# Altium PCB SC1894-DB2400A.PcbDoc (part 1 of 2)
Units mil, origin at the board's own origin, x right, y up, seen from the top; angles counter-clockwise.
Board outline 1800 x 1000 mil, 4 copper layers (L1 TOP, L2 GND, L3 PWR, L4  BOT), stack 35.4 mil thick; 139 components, 91 nets, 318 pads, 589 vias.
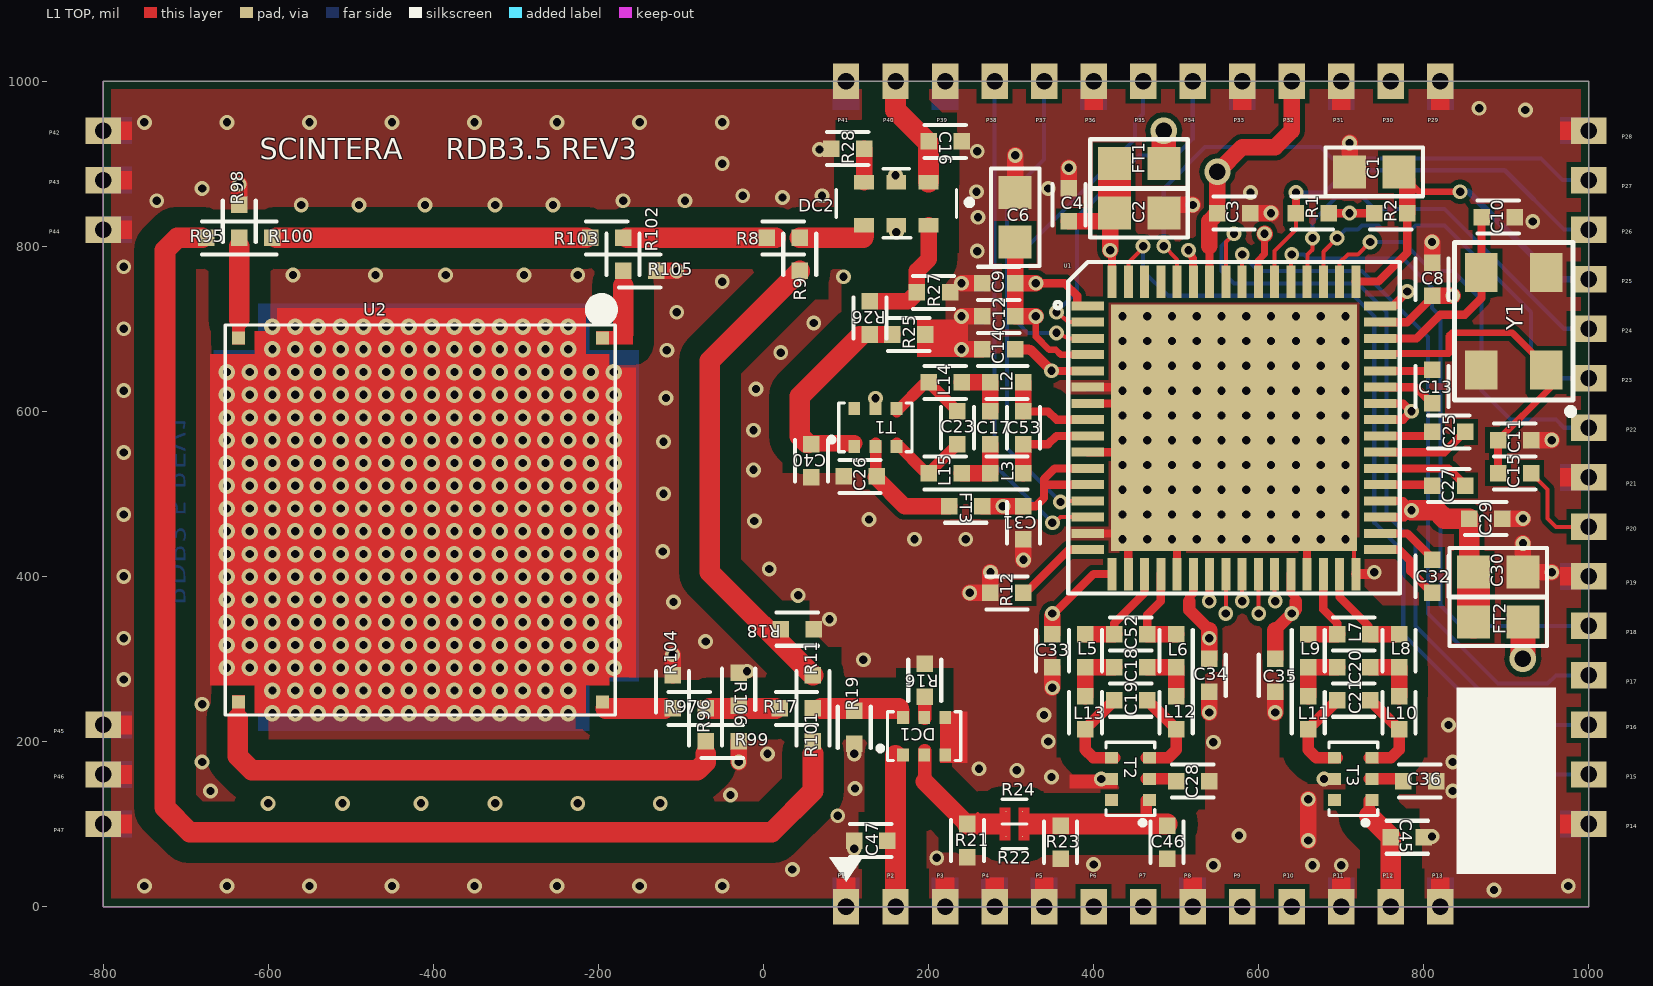
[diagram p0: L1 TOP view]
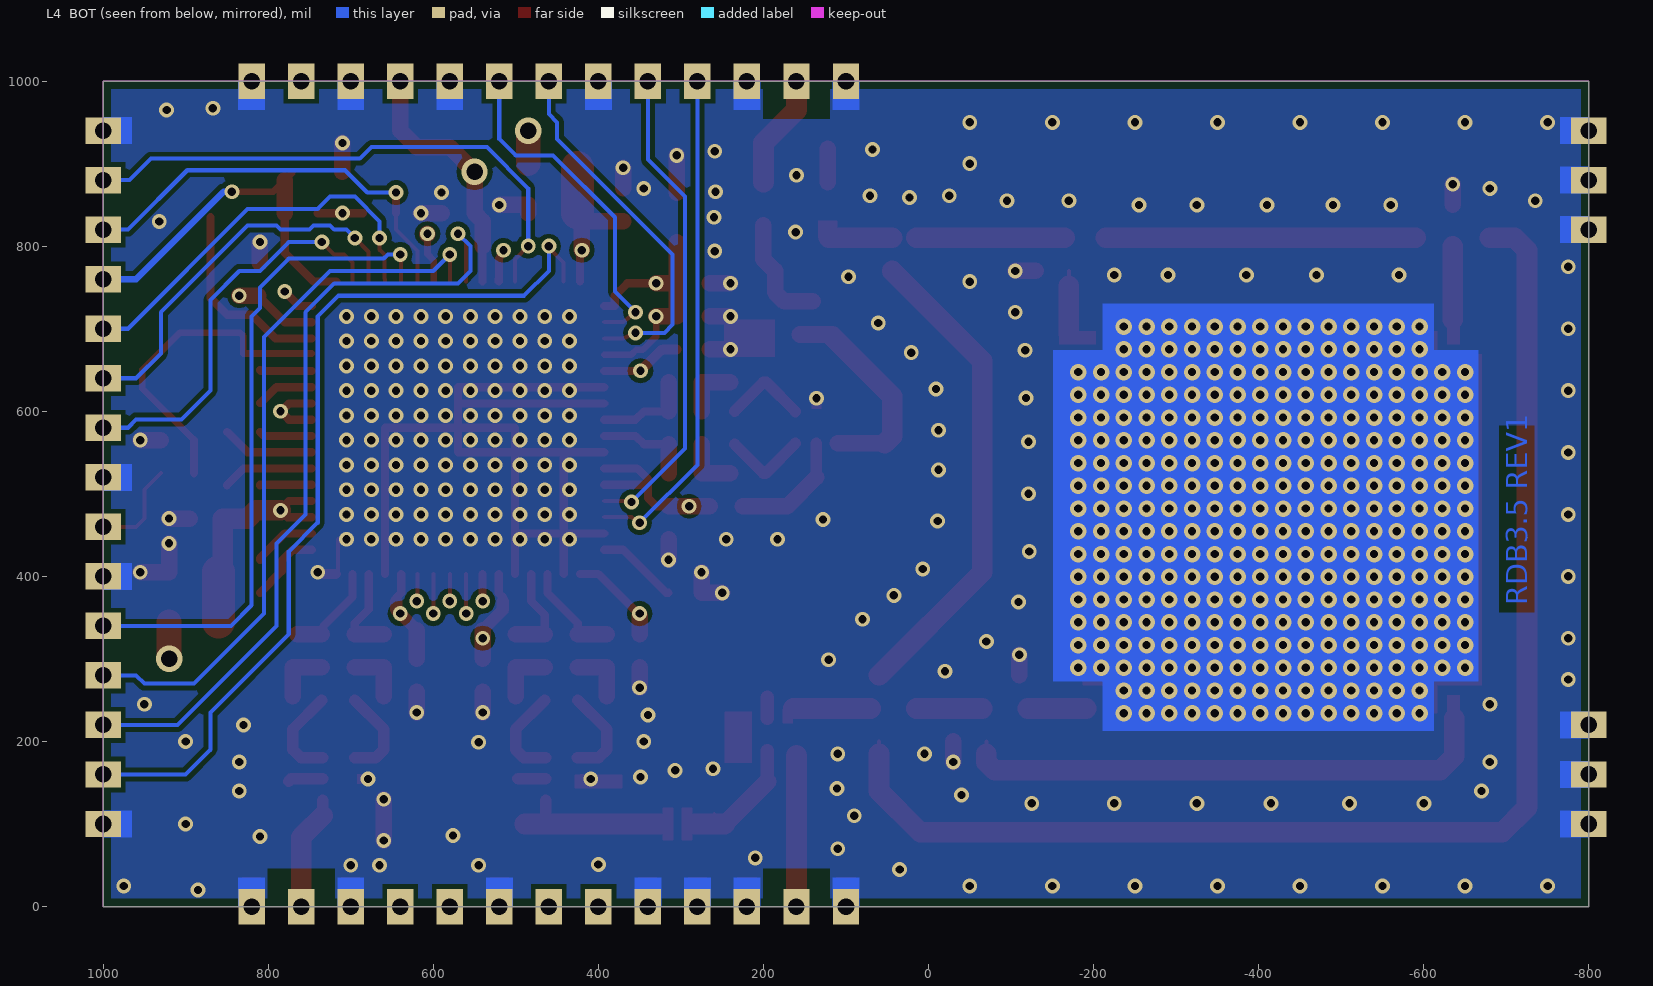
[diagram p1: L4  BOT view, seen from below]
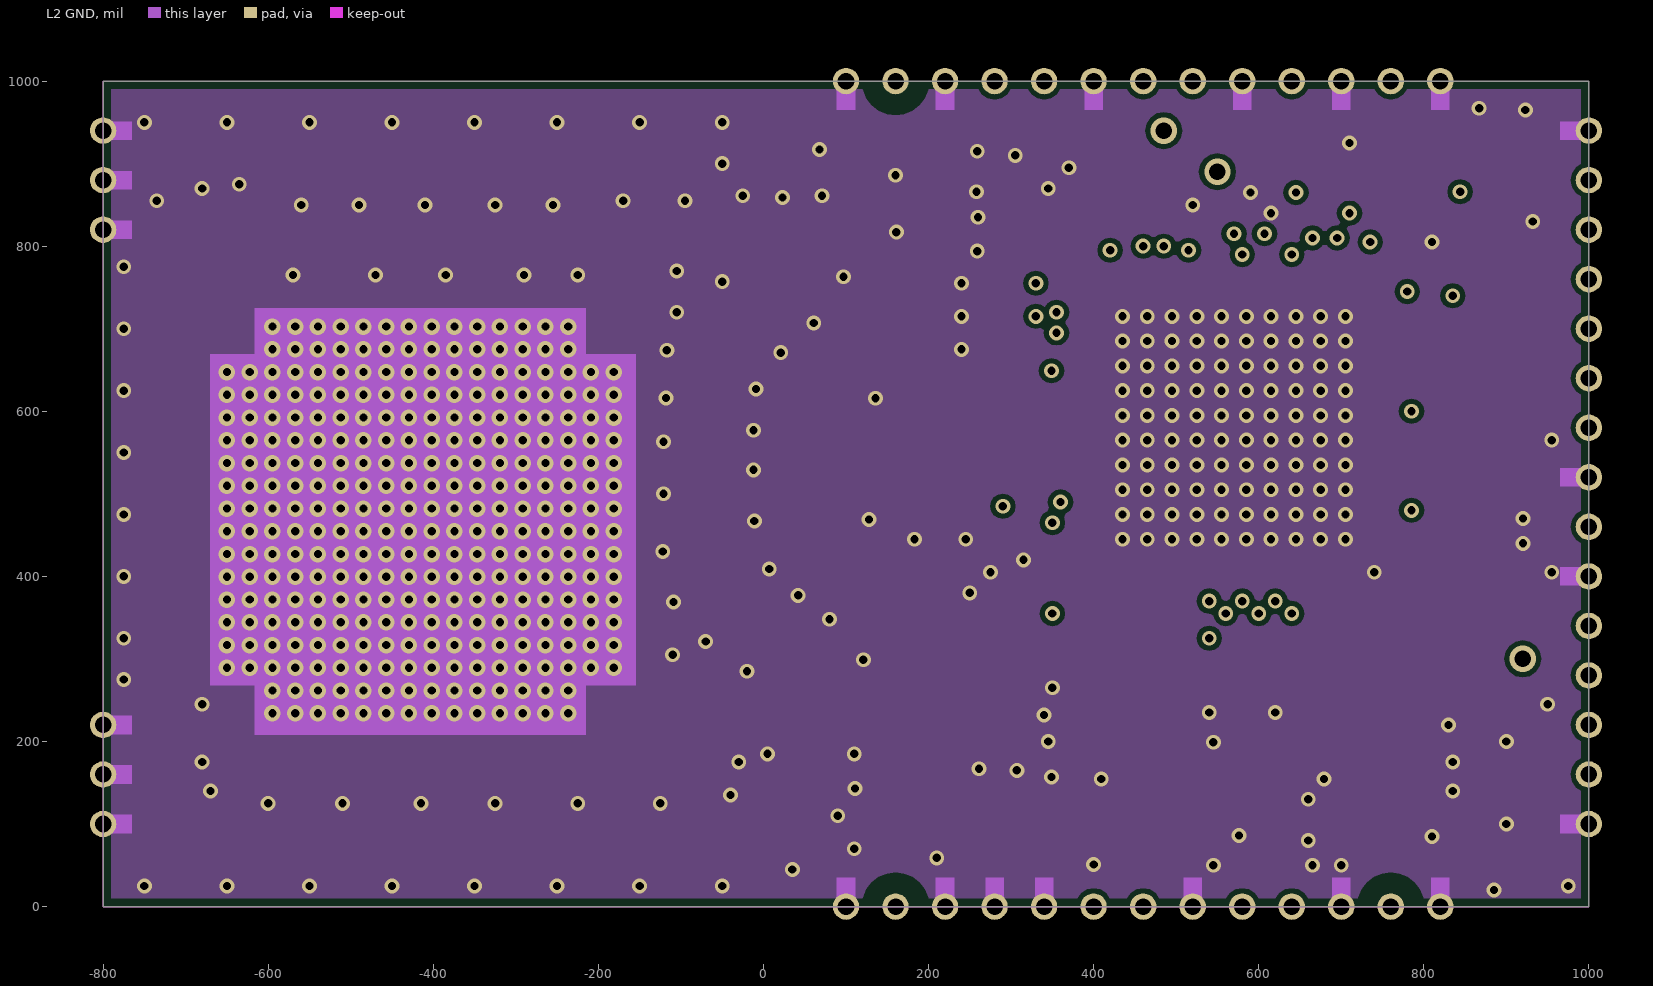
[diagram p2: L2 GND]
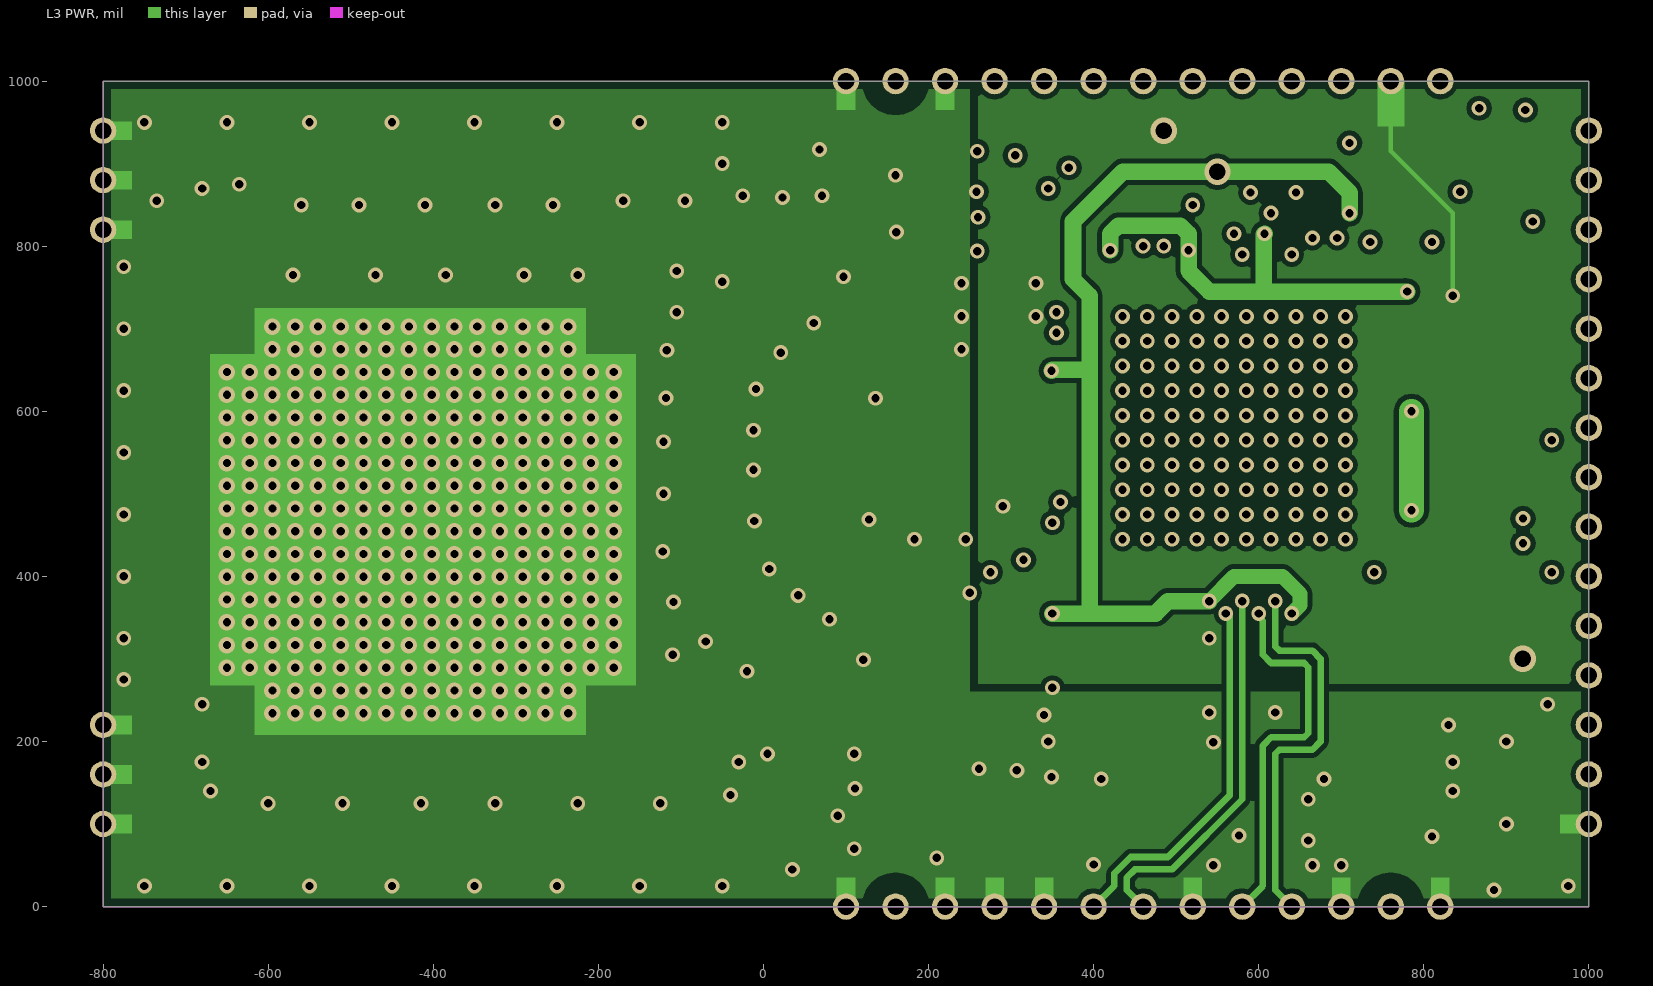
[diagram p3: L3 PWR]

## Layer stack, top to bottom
Solder Mask Top: solder mask 0.4, Solder Resist, Dk 3.5
L1 TOP: signal copper 1.35
Dielectric1: dielectric 10, FR-4, Dk 4.3
L2 GND: signal copper 1.35
Dielectric2: dielectric 10, FR-4, Dk 4.3
L3 PWR: signal copper 1.35
Dielectric3: dielectric 10, FR-4, Dk 4.3
L4  BOT: signal copper 1.35
Solder Mask Bottom: solder mask 0.4, Solder Resist, Dk 3.5

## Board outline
-800,1000 -800,0 1000,0 1000,1000

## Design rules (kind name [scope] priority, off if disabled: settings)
Clearance "RF Trace Clearance" [InNetClass('RF')] p1: gap=25
Clearance "'Default' PADS rule_24" [(IsTrack Or IsArc) vs IsSMTPin] p2: gap=6
Clearance "'Default' PADS rule_23" [IsSMTPin vs (IsTrack Or IsArc)] p3: gap=6
Clearance "'Default' PADS rule_22" [(IsTrack Or IsArc) vs IsThruPin] p4: gap=6
Clearance "'Default' PADS rule_21" [IsThruPin vs (IsTrack Or IsArc)] p5: gap=6
Clearance "'Default' PADS rule_20" [All] p6: gap=6
Clearance "'Default' PADS rule_19" [(IsTrack Or IsArc) vs (IsTrack Or IsArc)] p7: gap=6
Clearance "'Default' PADS rule_18" [All] p8: gap=6
Clearance "'Default' PADS rule_15" [IsVia vs IsVia] p9: gap=6
ComponentClearance "'Default' PADS rule_12" [All] p1: gap=6 collisioncheckmode=3 verticalgap=10 showdistances=FALSE
FlightTimeFalling "'Default' PADS rule_6" [All] p1: maximum=10.00
FlightTimeRising "'Default' PADS rule_5" [All] p1: maximum=10.00
Length "'Default' PADS rule" [All] p1: maxlimit=50000 minlimit=0
MatchedLengths "'Default' PADS rule_7" [InNetClass('All Nets')] p1: tolerance=200 checknetsindiffpair=TRUE checkdiffpairvsdiffpair=TRUE checkothers=TRUE
MaxMinImpedance "'Default' PADS rule_4" [All] p1: minimum=50.00 maximum=150.0
ParallelSegment "'Default' PADS rule_3" [All] p1: limit=1000 gap=200
ParallelSegment "'Default' PADS rule_2" [All] p2: limit=1000 gap=200
PlaneClearance "'Net' PADS rule_50" [InNet('N16778151')] p1: clearance=20
PlaneClearance "'Net' PADS rule_49" [InNet('N16798748')] p2: clearance=20
PlaneClearance "'Net' PADS rule_48" [InNet('GND')] p3: clearance=8
PlaneClearance "'Net' PADS rule_46" [InNet('N16820786')] p4: clearance=20
PlaneClearance "'Net' PADS rule_45" [InNet('N16798802')] p5: clearance=20
PlaneClearance "'Net' PADS rule_44" [InNet('N16778850')] p6: clearance=20
PlaneClearance "'Net' PADS rule_43" [InNet('RFIN')] p7: clearance=20
PlaneClearance "'Net' PADS rule_42" [InNet('N16837562')] p8: clearance=20
PlaneClearance "'Net' PADS rule_41" [InNet('N16905883')] p9: clearance=20
PlaneClearance "'Net' PADS rule_40" [InNet('N16809609')] p10: clearance=20
PlaneClearance "'Net' PADS rule_39" [InNet('N16837983')] p11: clearance=20
PlaneClearance "'Net' PADS rule_38" [InNet('N16886954')] p12: clearance=20
PlaneClearance "'Net' PADS rule_37" [InNet('N16852193')] p13: clearance=20
PlaneClearance "'Net' PADS rule_36" [InNet('N16907208')] p14: clearance=10
PlaneClearance "'Net' PADS rule_35" [InNet('N16864474')] p15: clearance=20
PlaneClearance "'Net' PADS rule_34" [InNet('N16853064')] p16: clearance=20
PlaneClearance "'Net' PADS rule_33" [InNet('N16810438')] p17: clearance=20
PlaneClearance "'Net' PADS rule_32" [InNet('N16780104')] p18: clearance=20
PlaneClearance "'Net' PADS rule_31" [InNet('N16780111')] p19: clearance=20
PlaneClearance "'Net' PADS rule_30" [InNet('N16778643')] p20: clearance=20
PlaneClearance "'Net' PADS rule_29" [InNet('N16778883')] p21: clearance=20
PlaneClearance "'Net' PADS rule_28" [InNet('N16779391')] p22: clearance=20
PlaneClearance "'Net' PADS rule_27" [InNet('N16778942')] p23: clearance=20
PlaneClearance "'Net' PADS rule_26" [InNet('RFFB')] p24: clearance=20
PlaneClearance "'Net' PADS rule_25" [InNet('N16779395')] p25: clearance=20
PlaneClearance "'Net' PADS rule" [InNet('N16780222')] p26: clearance=20
PlaneClearance "'Default' PADS rule_14" [All] p27: clearance=6
PlaneConnect "Power Plane Connect Style - Via from round thru-hole global defaults" [IsVia] p1: planeconnectstyle=Direct reliefexpansion=20 reliefentries=4 reliefconductorwidth=15 reliefairgap=10
PlaneConnect "Power Plane Connect Style - Round thru-hole pad from global defaults" [IsPad And OnMultiLayer And (PadShape_MidLayer1 = 'Round') And (PadXSize_MidLayer1 = PadYSize_MidLayer1)] p2: planeconnectstyle=Direct reliefexpansion=20 reliefentries=4 reliefconductorwidth=15 reliefairgap=10
PlaneConnect "Power Plane Connect Style - Square thru-hole pad from global defaults" [IsPad And OnMultiLayer And ((PadShape_MidLayer1 = 'Rectangular') Or (PadShape_MidLayer1 = 'Octagonal') Or (PadShape_MidLayer1 = 'Rounded Rectangle')) And (PadXSize_MidLayer1 = PadYSize_MidLayer1)] p3: planeconnectstyle=Direct reliefexpansion=20 reliefentries=4 reliefconductorwidth=15 reliefairgap=10
PlaneConnect "Power Plane Connect Style - Rect thru-hole pad from global defaults" [IsPad And OnMultiLayer And ((PadShape_MidLayer1 = 'Rectangular') Or (PadShape_MidLayer1 = 'Octagonal') Or (PadShape_MidLayer1 = 'Rounded Rectangle')) And (PadXSize_MidLayer1 <> PadYSize_MidLayer1)] p4: planeconnectstyle=Direct reliefexpansion=20 reliefentries=4 reliefconductorwidth=15 reliefairgap=10
PlaneConnect "Power Plane Connect Style - Square-rect thru-hole pad from global defaults" [IsPad And OnMultiLayer And (PadShape_MidLayer1 = 'Rounded Rectangle') And (PadXSize_MidLayer1 = PadYSize_MidLayer1) And (Pad_CornerRadius_MidLayer1 = '0%')] p5: planeconnectstyle=Direct reliefexpansion=20 reliefentries=4 reliefconductorwidth=15 reliefairgap=10
PlaneConnect "Power Plane Connect Style - Oval thru-hole pad from global defaults" [IsPad And OnMultiLayer And (PadShape_MidLayer1 = 'Round') And (PadXSize_MidLayer1 <> PadYSize_MidLayer1)] p6: planeconnectstyle=Direct reliefexpansion=20 reliefentries=4 reliefconductorwidth=15 reliefairgap=10
PlaneConnect "Power Plane Connect Style - Round-oval thru-hole pad from global defaults" [IsPad And OnMultiLayer And (PadShape_MidLayer1 = 'Rounded Rectangle') And (PadXSize_MidLayer1 = PadYSize_MidLayer1) And (Pad_CornerRadius_MidLayer1 = '100%')] p7: planeconnectstyle=Direct reliefexpansion=20 reliefentries=4 reliefconductorwidth=15 reliefairgap=10
PolygonConnect "Polygon Connect Style - L4  BOT Round SMD from global defaults" [IsSMTPin And (PadShape_BottomLayer = 'Round') And (PadXSize_BottomLayer = PADYSize_BottomLayer) vs Layer = 'L4  BOT'] p1: connectstyle=Direct reliefconductorwidth=10 reliefentries=4 polygonreliefangle="45 Angle" airgapwidth=10
PolygonConnect "Polygon Connect Style - L1 TOP Round SMD from global defaults" [IsSMTPin And (PadShape_TopLayer = 'Round') And (PadXSize_TopLayer = PADYSize_TopLayer) vs Layer = 'L1 TOP'] p2: connectstyle=Direct reliefconductorwidth=10 reliefentries=4 polygonreliefangle="45 Angle" airgapwidth=10
PolygonConnect "Polygon Connect Style - L4  BOT Square SMD from global defaults 1" [IsSMTPin And (PadShape_BottomLayer = 'Rectangular') And (PadXSize_BottomLayer = PADYSize_BottomLayer) vs Layer = 'L4  BOT'] p3: connectstyle=Direct reliefconductorwidth=10 reliefentries=4 polygonreliefangle="45 Angle" airgapwidth=10
PolygonConnect "Polygon Connect Style - L4  BOT Square SMD from global defaults 2" [IsSMTPin And (PadShape_BottomLayer = 'Octagonal') And (PadXSize_BottomLayer = PADYSize_BottomLayer) vs Layer = 'L4  BOT'] p4: connectstyle=Direct reliefconductorwidth=10 reliefentries=4 polygonreliefangle="45 Angle" airgapwidth=10
PolygonConnect "Polygon Connect Style - L4  BOT Square SMD from global defaults 3" [IsSMTPin And (PadShape_BottomLayer = 'Rounded Rectangle') And (PadXSize_BottomLayer = PADYSize_BottomLayer) vs Layer = 'L4  BOT'] p5: connectstyle=Direct reliefconductorwidth=10 reliefentries=4 polygonreliefangle="45 Angle" airgapwidth=10
PolygonConnect "Polygon Connect Style - L1 TOP Square SMD from global defaults 1" [IsSMTPin And (PadShape_TopLayer = 'Rectangular') And (PadXSize_TopLayer = PADYSize_TopLayer) vs Layer = 'L1 TOP'] p6: connectstyle=Direct reliefconductorwidth=10 reliefentries=4 polygonreliefangle="45 Angle" airgapwidth=10
PolygonConnect "Polygon Connect Style - L1 TOP Square SMD from global defaults 2" [IsSMTPin And (PadShape_TopLayer = 'Octagonal') And (PadXSize_TopLayer = PADYSize_TopLayer) vs Layer = 'L1 TOP'] p7: connectstyle=Direct reliefconductorwidth=10 reliefentries=4 polygonreliefangle="45 Angle" airgapwidth=10
PolygonConnect "Polygon Connect Style - L1 TOP Square SMD from global defaults 3" [IsSMTPin And (PadShape_TopLayer = 'Rounded Rectangle') And (PadXSize_TopLayer = PADYSize_TopLayer) vs Layer = 'L1 TOP'] p8: connectstyle=Direct reliefconductorwidth=10 reliefentries=4 polygonreliefangle="45 Angle" airgapwidth=10
PolygonConnect "Polygon Connect Style - L4  BOT Rect SMD from global defaults 1" [IsSMTPin And (PadShape_BottomLayer = 'Rectangular') And (PadXSize_BottomLayer <> PADYSize_BottomLayer) vs Layer = 'L4  BOT'] p9: connectstyle=Direct reliefconductorwidth=10 reliefentries=4 polygonreliefangle="45 Angle" airgapwidth=10
PolygonConnect "Polygon Connect Style - L4  BOT Rect SMD from global defaults 2" [IsSMTPin And (PadShape_BottomLayer = 'Octagonal') And (PadXSize_BottomLayer <> PADYSize_BottomLayer) vs Layer = 'L4  BOT'] p10: connectstyle=Direct reliefconductorwidth=10 reliefentries=4 polygonreliefangle="45 Angle" airgapwidth=10
PolygonConnect "Polygon Connect Style - L4  BOT Rect SMD from global defaults 3" [IsSMTPin And (PadShape_BottomLayer = 'Rounded Rectangle') And (PadXSize_BottomLayer <> PADYSize_BottomLayer) vs Layer = 'L4  BOT'] p11: connectstyle=Direct reliefconductorwidth=10 reliefentries=4 polygonreliefangle="45 Angle" airgapwidth=10
PolygonConnect "Polygon Connect Style - L4  BOT Square-rect SMD pad from global defaults" [IsSMTPin And (PadShape_BottomLayer = 'Rounded Rectangle') And (PadXSize_BottomLayer = PADYSize_BottomLayer) And (Pad_CornerRadius_BottomLayer = '0%') vs Layer = 'L4  BOT'] p12: connectstyle=Direct reliefconductorwidth=10 reliefentries=4 polygonreliefangle="45 Angle" airgapwidth=10
PolygonConnect "Polygon Connect Style - L1 TOP Rect SMD from global defaults 1" [IsSMTPin And (PadShape_TopLayer = 'Rectangular') And (PadXSize_TopLayer <> PADYSize_TopLayer) vs Layer = 'L1 TOP'] p13: connectstyle=Direct reliefconductorwidth=10 reliefentries=4 polygonreliefangle="45 Angle" airgapwidth=10
PolygonConnect "Polygon Connect Style - L1 TOP Rect SMD from global defaults 2" [IsSMTPin And (PadShape_TopLayer = 'Octagonal') And (PadXSize_TopLayer <> PADYSize_TopLayer) vs Layer = 'L1 TOP'] p14: connectstyle=Direct reliefconductorwidth=10 reliefentries=4 polygonreliefangle="45 Angle" airgapwidth=10
PolygonConnect "Polygon Connect Style - L1 TOP Rect SMD from global defaults 3" [IsSMTPin And (PadShape_TopLayer = 'Rounded Rectangle') And (PadXSize_TopLayer <> PADYSize_TopLayer) vs Layer = 'L1 TOP'] p15: connectstyle=Direct reliefconductorwidth=10 reliefentries=4 polygonreliefangle="45 Angle" airgapwidth=10
PolygonConnect "Polygon Connect Style - L1 TOP Square-rect SMD pad from global defaults" [IsSMTPin And (PadShape_TopLayer = 'Rounded Rectangle') And (PadXSize_TopLayer = PADYSize_TopLayer) And (Pad_CornerRadius_TopLayer = '0%') vs Layer = 'L1 TOP'] p16: connectstyle=Direct reliefconductorwidth=10 reliefentries=4 polygonreliefangle="45 Angle" airgapwidth=10
PolygonConnect "Polygon Connect Style - L4  BOT Oval SMD from global defaults" [IsSMTPin And (PadShape_BottomLayer = 'Round') And (PadXSize_BottomLayer <> PADYSize_BottomLayer) vs Layer = 'L4  BOT'] p17: connectstyle=Direct reliefconductorwidth=10 reliefentries=4 polygonreliefangle="45 Angle" airgapwidth=10
PolygonConnect "Polygon Connect Style - L4  BOT Round-oval SMD pad from global defaults" [IsSMTPin And (PadShape_BottomLayer = 'Rounded Rectangle') And (PadXSize_BottomLayer = PADYSize_BottomLayer) And (Pad_CornerRadius_BottomLayer = '100%') vs Layer = 'L4  BOT'] p18: connectstyle=Direct reliefconductorwidth=10 reliefentries=4 polygonreliefangle="45 Angle" airgapwidth=10
PolygonConnect "Polygon Connect Style - L1 TOP Oval SMD from global defaults" [IsSMTPin And (PadShape_TopLayer = 'Round') And (PadXSize_TopLayer <> PADYSize_TopLayer) vs Layer = 'L1 TOP'] p19: connectstyle=Direct reliefconductorwidth=10 reliefentries=4 polygonreliefangle="45 Angle" airgapwidth=10
PolygonConnect "Polygon Connect Style - L1 TOP Round-oval SMD pad from global defaults" [IsSMTPin And (PadShape_TopLayer = 'Rounded Rectangle') And (PadXSize_TopLayer = PADYSize_TopLayer) And (Pad_CornerRadius_TopLayer = '100%') vs Layer = 'L1 TOP'] p20: connectstyle=Direct reliefconductorwidth=10 reliefentries=4 polygonreliefangle="45 Angle" airgapwidth=10
PolygonConnect "Polygon Connect Style - Via from round thru-hole global defaults_53" [IsVia] p21: connectstyle=Direct reliefconductorwidth=15 reliefentries=4 polygonreliefangle="45 Angle" airgapwidth=10
PolygonConnect "Polygon Connect Style - L4  BOT Round thru-hole pad from global defaults" [IsPad And OnMultiLayer And (PadShape_BottomLayer = 'Round') And (PadXSize_BottomLayer = PADYSize_BottomLayer) vs Layer = 'L4  BOT'] p22: connectstyle=Direct reliefconductorwidth=15 reliefentries=4 polygonreliefangle="45 Angle" airgapwidth=10
PolygonConnect "Polygon Connect Style - Via from round thru-hole global defaults_52" [IsVia] p23: connectstyle=Direct reliefconductorwidth=15 reliefentries=4 polygonreliefangle="45 Angle" airgapwidth=10
PolygonConnect "Polygon Connect Style - L3 PWR Round thru-hole pad from global defaults" [IsPad And OnMultiLayer And (PadShape_MidLayer2 = 'Round') And (PadXSize_MidLayer2 = PADYSize_MidLayer2) vs Layer = 'L3 PWR'] p24: connectstyle=Direct reliefconductorwidth=15 reliefentries=4 polygonreliefangle="45 Angle" airgapwidth=10
PolygonConnect "Polygon Connect Style - Via from round thru-hole global defaults_51" [IsVia] p25: connectstyle=Direct reliefconductorwidth=15 reliefentries=4 polygonreliefangle="45 Angle" airgapwidth=10
PolygonConnect "Polygon Connect Style - L2 GND Round thru-hole pad from global defaults" [IsPad And OnMultiLayer And (PadShape_MidLayer1 = 'Round') And (PadXSize_MidLayer1 = PADYSize_MidLayer1) vs Layer = 'L2 GND'] p26: connectstyle=Direct reliefconductorwidth=15 reliefentries=4 polygonreliefangle="45 Angle" airgapwidth=10
PolygonConnect "Polygon Connect Style - Via from round thru-hole global defaults" [IsVia] p27: connectstyle=Direct reliefconductorwidth=15 reliefentries=4 polygonreliefangle="45 Angle" airgapwidth=10
PolygonConnect "Polygon Connect Style - L1 TOP Round thru-hole pad from global defaults" [IsPad And OnMultiLayer And (PadShape_TopLayer = 'Round') And (PadXSize_TopLayer = PADYSize_TopLayer) vs Layer = 'L1 TOP'] p28: connectstyle=Direct reliefconductorwidth=15 reliefentries=4 polygonreliefangle="45 Angle" airgapwidth=10
PolygonConnect "Polygon Connect Style - L4  BOT Square thru-hole pad from global defaults" [IsPad And OnMultiLayer And ((PadShape_BottomLayer = 'Rectangular') Or (PadShape_BottomLayer = 'Octagonal') Or (PadShape_BottomLayer = 'Rounded Rectangle')) And (PadXSize_BottomLayer = PADYSize_BottomLayer) vs Layer = 'L4  BOT'] p29: connectstyle=Direct reliefconductorwidth=15 reliefentries=4 polygonreliefangle="45 Angle" airgapwidth=10
PolygonConnect "Polygon Connect Style - L3 PWR Square thru-hole pad from global defaults" [IsPad And OnMultiLayer And ((PadShape_MidLayer2 = 'Rectangular') Or (PadShape_MidLayer2 = 'Octagonal') Or (PadShape_MidLayer2 = 'Rounded Rectangle')) And (PadXSize_MidLayer2 = PADYSize_MidLayer2) vs Layer = 'L3 PWR'] p30: connectstyle=Direct reliefconductorwidth=15 reliefentries=4 polygonreliefangle="45 Angle" airgapwidth=10
PolygonConnect "Polygon Connect Style - L2 GND Square thru-hole pad from global defaults" [IsPad And OnMultiLayer And ((PadShape_MidLayer1 = 'Rectangular') Or (PadShape_MidLayer1 = 'Octagonal') Or (PadShape_MidLayer1 = 'Rounded Rectangle')) And (PadXSize_MidLayer1 = PADYSize_MidLayer1) vs Layer = 'L2 GND'] p31: connectstyle=Direct reliefconductorwidth=15 reliefentries=4 polygonreliefangle="45 Angle" airgapwidth=10
PolygonConnect "Polygon Connect Style - L1 TOP Square thru-hole pad from global defaults" [IsPad And OnMultiLayer And ((PadShape_TopLayer = 'Rectangular') Or (PadShape_TopLayer = 'Octagonal') Or (PadShape_TopLayer = 'Rounded Rectangle')) And (PadXSize_TopLayer = PADYSize_TopLayer) vs Layer = 'L1 TOP'] p32: connectstyle=Direct reliefconductorwidth=15 reliefentries=4 polygonreliefangle="45 Angle" airgapwidth=10
PolygonConnect "Polygon Connect Style - L4  BOT Rect thru-hole pad from global defaults" [IsPad And OnMultiLayer And ((PadShape_BottomLayer = 'Rectangular') Or (PadShape_BottomLayer = 'Octagonal') Or (PadShape_BottomLayer = 'Rounded Rectangle')) And (PadXSize_BottomLayer <> PADYSize_BottomLayer) vs Layer = 'L4  BOT'] p33: connectstyle=Direct reliefconductorwidth=15 reliefentries=4 polygonreliefangle="45 Angle" airgapwidth=10
PolygonConnect "Polygon Connect Style - L4  BOT Square-rect thru-hole pad from global defaults" [IsPad And OnMultiLayer And (PadShape_BottomLayer = 'Rounded Rectangle') And (PadXSize_BottomLayer = PADYSize_BottomLayer) And (Pad_CornerRadius_BottomLayer = '0%') vs Layer = 'L4  BOT'] p34: connectstyle=Direct reliefconductorwidth=15 reliefentries=4 polygonreliefangle="45 Angle" airgapwidth=10
PolygonConnect "Polygon Connect Style - L3 PWR Rect thru-hole pad from global defaults" [IsPad And OnMultiLayer And ((PadShape_MidLayer2 = 'Rectangular') Or (PadShape_MidLayer2 = 'Octagonal') Or (PadShape_MidLayer2 = 'Rounded Rectangle')) And (PadXSize_MidLayer2 <> PADYSize_MidLayer2) vs Layer = 'L3 PWR'] p35: connectstyle=Direct reliefconductorwidth=15 reliefentries=4 polygonreliefangle="45 Angle" airgapwidth=10
PolygonConnect "Polygon Connect Style - L3 PWR Square-rect thru-hole pad from global defaults" [IsPad And OnMultiLayer And (PadShape_MidLayer2 = 'Rounded Rectangle') And (PadXSize_MidLayer2 = PADYSize_MidLayer2) And (Pad_CornerRadius_MidLayer2 = '0%') vs Layer = 'L3 PWR'] p36: connectstyle=Direct reliefconductorwidth=15 reliefentries=4 polygonreliefangle="45 Angle" airgapwidth=10
PolygonConnect "Polygon Connect Style - L2 GND Rect thru-hole pad from global defaults" [IsPad And OnMultiLayer And ((PadShape_MidLayer1 = 'Rectangular') Or (PadShape_MidLayer1 = 'Octagonal') Or (PadShape_MidLayer1 = 'Rounded Rectangle')) And (PadXSize_MidLayer1 <> PADYSize_MidLayer1) vs Layer = 'L2 GND'] p37: connectstyle=Direct reliefconductorwidth=15 reliefentries=4 polygonreliefangle="45 Angle" airgapwidth=10
PolygonConnect "Polygon Connect Style - L2 GND Square-rect thru-hole pad from global defaults" [IsPad And OnMultiLayer And (PadShape_MidLayer1 = 'Rounded Rectangle') And (PadXSize_MidLayer1 = PADYSize_MidLayer1) And (Pad_CornerRadius_MidLayer1 = '0%') vs Layer = 'L2 GND'] p38: connectstyle=Direct reliefconductorwidth=15 reliefentries=4 polygonreliefangle="45 Angle" airgapwidth=10
PolygonConnect "Polygon Connect Style - L1 TOP Rect thru-hole pad from global defaults" [IsPad And OnMultiLayer And ((PadShape_TopLayer = 'Rectangular') Or (PadShape_TopLayer = 'Octagonal') Or (PadShape_TopLayer = 'Rounded Rectangle')) And (PadXSize_TopLayer <> PADYSize_TopLayer) vs Layer = 'L1 TOP'] p39: connectstyle=Direct reliefconductorwidth=15 reliefentries=4 polygonreliefangle="45 Angle" airgapwidth=10
PolygonConnect "Polygon Connect Style - L1 TOP Square-rect thru-hole pad from global defaults" [IsPad And OnMultiLayer And (PadShape_TopLayer = 'Rounded Rectangle') And (PadXSize_TopLayer = PADYSize_TopLayer) And (Pad_CornerRadius_TopLayer = '0%') vs Layer = 'L1 TOP'] p40: connectstyle=Direct reliefconductorwidth=15 reliefentries=4 polygonreliefangle="45 Angle" airgapwidth=10
PolygonConnect "Polygon Connect Style - L4  BOT Oval thru-hole pad from global defaults" [IsPad And OnMultiLayer And (PadShape_BottomLayer = 'Round') And (PadXSize_BottomLayer <> PADYSize_BottomLayer) vs Layer = 'L4  BOT'] p41: connectstyle=Direct reliefconductorwidth=15 reliefentries=4 polygonreliefangle="45 Angle" airgapwidth=10
PolygonConnect "Polygon Connect Style - L4  BOT Round-oval thru-hole pad from global defaults" [IsPad And OnMultiLayer And (PadShape_BottomLayer = 'Rounded Rectangle') And (PadXSize_BottomLayer = PADYSize_BottomLayer) And (Pad_CornerRadius_BottomLayer = '100%') vs Layer = 'L4  BOT'] p42: connectstyle=Direct reliefconductorwidth=15 reliefentries=4 polygonreliefangle="45 Angle" airgapwidth=10
PolygonConnect "Polygon Connect Style - L3 PWR Oval thru-hole pad from global defaults" [IsPad And OnMultiLayer And (PadShape_MidLayer2 = 'Round') And (PadXSize_MidLayer2 <> PADYSize_MidLayer2) vs Layer = 'L3 PWR'] p43: connectstyle=Direct reliefconductorwidth=15 reliefentries=4 polygonreliefangle="45 Angle" airgapwidth=10
PolygonConnect "Polygon Connect Style - L3 PWR Round-oval thru-hole pad from global defaults" [IsPad And OnMultiLayer And (PadShape_MidLayer2 = 'Rounded Rectangle') And (PadXSize_MidLayer2 = PADYSize_MidLayer2) And (Pad_CornerRadius_MidLayer2 = '100%') vs Layer = 'L3 PWR'] p44: connectstyle=Direct reliefconductorwidth=15 reliefentries=4 polygonreliefangle="45 Angle" airgapwidth=10
PolygonConnect "Polygon Connect Style - L2 GND Oval thru-hole pad from global defaults" [IsPad And OnMultiLayer And (PadShape_MidLayer1 = 'Round') And (PadXSize_MidLayer1 <> PADYSize_MidLayer1) vs Layer = 'L2 GND'] p45: connectstyle=Direct reliefconductorwidth=15 reliefentries=4 polygonreliefangle="45 Angle" airgapwidth=10
PolygonConnect "Polygon Connect Style - L2 GND Round-oval thru-hole pad from global defaults" [IsPad And OnMultiLayer And (PadShape_MidLayer1 = 'Rounded Rectangle') And (PadXSize_MidLayer1 = PADYSize_MidLayer1) And (Pad_CornerRadius_MidLayer1 = '100%') vs Layer = 'L2 GND'] p46: connectstyle=Direct reliefconductorwidth=15 reliefentries=4 polygonreliefangle="45 Angle" airgapwidth=10
PolygonConnect "Polygon Connect Style - L1 TOP Oval thru-hole pad from global defaults" [IsPad And OnMultiLayer And (PadShape_TopLayer = 'Round') And (PadXSize_TopLayer <> PADYSize_TopLayer) vs Layer = 'L1 TOP'] p47: connectstyle=Direct reliefconductorwidth=15 reliefentries=4 polygonreliefangle="45 Angle" airgapwidth=10
PolygonConnect "Polygon Connect Style - L1 TOP Round-oval thru-hole pad from global defaults" [IsPad And OnMultiLayer And (PadShape_TopLayer = 'Rounded Rectangle') And (PadXSize_TopLayer = PADYSize_TopLayer) And (Pad_CornerRadius_TopLayer = '100%') vs Layer = 'L1 TOP'] p48: connectstyle=Direct reliefconductorwidth=15 reliefentries=4 polygonreliefangle="45 Angle" airgapwidth=10
PolygonConnect [All] p49: connectstyle=Relief reliefconductorwidth=10 reliefentries=4 polygonreliefangle="90 Angle" airgapwidth=10
RoutingLayers "'Default' PADS rule_10" [All] p1: top layer_v5=TRUE mid layer 1_v5=TRUE mid layer 2_v5=TRUE bottom layer_v5=TRUE
RoutingPriority "'Default' PADS rule_9" [All] p1: routingpriority=3
RoutingTopology "'Default' PADS rule_8" [All] p1: topology=Shortest
RoutingVias "'Default' PADS rule_11" [All] p1: holewidth=10 width=18 viastyle="Through Hole" minholewidth=10 minwidth=18 maxholewidth=10 maxwidth=18
SMDToCorner "'Default' PADS rule_16" [All] p1: distance=60000
SMDToPlane "'Default' PADS rule_17" [All] p1: distance=60000
SilkToSolderMaskClearance SilkscreenOverComponentPads [IsPad] p1: minsilkscreentomaskgap=10 clearancetoexposedcopper=TRUE
SolderMaskExpansion "Solder Mask Expansion from CAM settings" [All] p1: expansion=5
Width "'Net' PADS rule_47" [InNet('GND')] p1: maxlimit=50 minlimit=4 preferedwidth=20
Width "'Default' PADS rule_13" [All] p2: maxlimit=50 minlimit=4 preferedwidth=5
23 further rules are at their usual default settings.

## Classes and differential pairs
net class RF: N16778055 N16778107 N16778151 N16778848 N16778878 N16778883 N16778942 N16779024 N16779035 N16779391 N16779395 N16780104 N16780111 N16780222 N16780244 N16798679 N16798683 N16798687 N16798691 N16798746 N16798748 N16798750 N16798758 N16798802 N16798852 N16798884 N16798892 N16798938 N16809609 N16810438 N16820786 N16837562 N16837983 N16842500 N16852193 N16853064 N16864474 N16886954 N16905362 N16905883 N16907208 RFFB RFIN RFIN_CPL_50OHM RFIN_CPL_CPL RFOUT RFOUT_BLN_SE RFOUT_BLN_SE_DCBL RFOUT_CPL_50OHM RFOUT_CPL_IN

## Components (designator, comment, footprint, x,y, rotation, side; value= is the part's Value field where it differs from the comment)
C1 "0603" 0603 740,890 r180 top
C2 "0603" 0603 455,840 r180 top
C3 "0402" 0402 570,840 r180 top
C4 "0402" 0402 370,850 r90 top
C6 "0603" 0603 305,835 r90 top
C8 "0402" 0402 810,760 r90 top
C9 "0402" 0402 285,755 r180 top
C10 "0402" 0402 890,835.13 r0 top
C11 "0402" 0402 910,565 r0 top
C12 "0402" 0402 285,715 r180 top
C13 "0402" 0402 810,630 r270 top
C14 "0402" 0402 285,675 r180 top
C15 "0402" 0402 910,525 r0 top
C16 "0402" 0402 220,927 r0 top
C17 "0402" 0402 275,580 r270 top
C18 "0402" 0402 445,290 r0 top
C19 "0402" 0402 445,250 r0 top
C20 "0402" 0402 715,290 r0 top
C21 "0402" 0402 715,250 r0 top
C23 "0402" 0402 235,580 r270 top
C25 "0402" 0402 830,575 r0 top
C26 "0402" 0402 117,521 r0 top
C27 "0402" 0402 830,510 r180 top
C28 "0402" 0402 520,152 r180 top
C29 "0402" 0402 875,470 r0 top
C30 "0603" 0603 890,405 r0 top
C31 "0402" 0402 315,465 r270 top
C32 "0402" 0402 810,400 r270 top
C33 "0402" 0402 350,310 r270 top
C34 "0402" 0402 540,280 r270 top
C35 "0402" 0402 620,280 r270 top
C36 "0402" 0402 795,152 r0 top
C40 "0402" 0402 58,540 r270 top
C45 "0402" 0402 780,84 r0 top
C46 "0402" 0402 489,78 r270 top
C47 "0402" 0402 130,80 r180 top
C52 "0402" 0402 445,330 r0 top
C53 "0402" 0402 315,580 r90 top
DC1 "" "0805 COUPLER ANAREN" 234,231 r180 top
DC2 "" BDCN-7-25+ 98,820 r0 top
FT1 "0603" 0603 455,900 r0 top
FT2 "0603" 0603 890,345 r180 top
FT3 "0402" 0402 245,485 r180 top
L2 "0402" 0402 295,635 r0 top
L3 "0402" 0402 295,525 r180 top
L5 "0402" 0402 390,310 r90 top
L6 "0402" 0402 500,310 r270 top
L7 "0402" 0402 715,330 r0 top
L8 "0402" 0402 770,310 r270 top
L9 "0402" 0402 660,310 r90 top
L10 "0402" 0402 770,235 r270 top
L11 "0402" 0402 660,235 r90 top
L12 "0402" 0402 500,235 r270 top
L13 "0402" 0402 390,235 r90 top
L14 "0402" 0402 220,635 r0 top
L15 "0402" 0402 220,525 r180 top
P1 "PORT-1_M" PORT-1_M 100,0 r0 top
P2 "PORT-1_M" PORT-1_M 160,0 r0 top
P3 "PORT-1_M" PORT-1_M 220,0 r0 top
P4 "PORT-1_M" PORT-1_M 280,0 r0 top
P5 "PORT-1_M" PORT-1_M 340,0 r0 top
P6 "PORT-1_M" PORT-1_M 400,0 r0 top
P7 "PORT-1_M" PORT-1_M 460,0 r0 top
P8 "PORT-1_M" PORT-1_M 520,0 r0 top
P9 "PORT-1_M" PORT-1_M 580,0 r0 top
P10 "PORT-1_M" PORT-1_M 640,0 r0 top
P11 "PORT-1_M" PORT-1_M 700,0 r180 top
P12 "PORT-1_M" PORT-1_M 760,0 r0 top
P13 "PORT-1_M" PORT-1_M 820,0 r180 top
P14 "PORT-1_M" PORT-1_M 1000,100 r90 top
P15 "PORT-1_M" PORT-1_M 1000,160 r90 top
P16 "PORT-1_M" PORT-1_M 1000,220 r90 top
P17 "PORT-1_M" PORT-1_M 1000,280 r90 top
P18 "PORT-1_M" PORT-1_M 1000,340 r90 top
P19 "PORT-1_M" PORT-1_M 1000,400 r90 top
P20 "PORT-1_M" PORT-1_M 1000,460 r90 top
P21 "PORT-1_M" PORT-1_M 1000,520 r90 top
P22 "PORT-1_M" PORT-1_M 1000,580 r90 top
P23 "PORT-1_M" PORT-1_M 1000,640 r90 top
P24 "PORT-1_M" PORT-1_M 1000,700 r90 top
P25 "PORT-1_M" PORT-1_M 1000,760 r90 top
P26 "PORT-1_M" PORT-1_M 1000,820 r90 top
P27 "PORT-1_M" PORT-1_M 1000,880 r90 top
P28 "PORT-1_M" PORT-1_M 1000,940 r90 top
P29 "PORT-1_M" PORT-1_M 820,1000 r0 top
P30 "PORT-1_M" PORT-1_M 760,1000 r0 top
P31 "PORT-1_M" PORT-1_M 700,1000 r0 top
P32 "PORT-1_M" PORT-1_M 640,1000 r0 top
P33 "PORT-1_M" PORT-1_M 580,1000 r0 top
P34 "PORT-1_M" PORT-1_M 520,1000 r0 top
P35 "PORT-1_M" PORT-1_M 460,1000 r0 top
P36 "PORT-1_M" PORT-1_M 400,1000 r0 top
P37 "PORT-1_M" PORT-1_M 340,1000 r0 top
P38 "PORT-1_M" PORT-1_M 280,1000 r0 top
P39 "PORT-1_M" PORT-1_M 220,1000 r180 top
P40 "PORT-1_M" PORT-1_M 160,1000 r0 top
P41 "PORT-1_M" PORT-1_M 100,1000 r180 top
P42 "PORT-1_M" PORT-1_M -800,940 r90 top
P43 "PORT-1_M" PORT-1_M -800,880 r90 top
P44 "PORT-1_M" PORT-1_M -800,820 r90 top
P45 "PORT-1_M" PORT-1_M -800,220 r90 top
P46 "PORT-1_M" PORT-1_M -800,160 r90 top
P47 "PORT-1_M" PORT-1_M -800,100 r90 top
R1 "0402" 0402 665,840 r0 top
R2 "0402" 0402 760,840 r0 top
R8 "0402" 0402 24,810 r180 top
R9 "0402" 0402 44,790 r90 top
R11 "0402" 0402 60,260 r270 top
R12 "0402" 0402 295,380 r0 top
R16 "0402" 0402 195.42,274 r90 top
R17 "0402" 0402 40,240 r180 top
R18 "0402" 0402 41,336 r0 top
R19 "0402" 0402 110,217 r270 top
R21 "0402" 0402 247,80 r270 top
R22 "" 0201_SMT 294,85 r0 top
R23 "0402" 0402 360,78 r270 top
R24 "" 0201_SMT 294,115 r0 top
R25 "0402" 0402 176,693 r0 top
R26 "0402" 0402 129,713 r90 top
R27 "0402" 0402 206,744 r0 top
R28 "0402" 0402 102,918.12 r0 top
R95 "0402" 0402 -655,810 r0 top
R96 "0402" 0402 -70,220 r90 top
R97 "0402" 0402 -90,240 r0 top
R98 "0402" 0402 -635,830 r270 top
R99 "0402" 0402 -50,200 r180 top
R100 "0402" 0402 -615,810 r180 top
R101 "0402" 0402 60,220 r270 top
R102 "0402" 0402 -170,790 r270 top
R103 "0402" 0402 -190,810 r180 top
R104 "0402" 0402 -110,260 r270 top
R105 "0402" 0402 -150,770 r180 top
R106 "0402" 0402 -30,263 r270 top
T1 "" "0805 BALUN ANAREN" 175,605 r180 top
T2 "" "0805 BALUN ANAREN" 420,194 r270 top
T3 "" "0805 BALUN ANAREN" 690,194 r270 top
U1 "QFN50P-RFPAL-CHAR" QFN50P-RFPAL-CHAR 570,580 r180 top
U2 "" DL246-A -644,240 r0 top
Y1 "" 278-20.0M 909,709 r90 top

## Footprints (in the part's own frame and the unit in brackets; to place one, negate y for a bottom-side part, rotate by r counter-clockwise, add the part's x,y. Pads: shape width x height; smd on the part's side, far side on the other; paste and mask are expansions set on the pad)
0201_SMT [mil] "0201_SMT_Res_Cap_Ind"
  rrect0% 1x1 smd mask+3: 0(0,0) 1(20,0)
  L1 TOP region: 15,-5 25,-5 25,5 15,5
  L1 TOP region: -5,-5 5,-5 5,5 -5,5
  silkscreen extent -5,-15 25,15
278-20.0M [mm] "278 Series Crystal from Oscilent"
  rect 1.2x1 smd paste+0 mask+0: 1(-1.5,-1) 2(1.5,-1) 3(1.5,1) 4(-1.5,1)
  silkscreen extent -2.85,-1.83 2.42,1.83
0402 [mil]
  rrect0% 20x20 smd: 1(-20,0) 2(20,0)
  silkscreen extent -25,-20 25,20
0603 [mil]
  rect 40x40 smd: 1(-30,0) 2(30,0)
  silkscreen extent -59,-30 59,30
"0805 BALUN ANAREN" [mm] "Anaren 0805 Balun (BD1722J50100A00 etc)"
  rect 0.36x0.4 smd: 1(1.65,1.205) 2(1,1.205) 3(0.35,1.205) 4(0.35,0.045) 5(1,0.045) 6(1.65,0.045)
  L1 TOP region: 0.775,-0.25 0.85,-0.175 0.85,0.05 1.15,0.05 1.15,-0.175 1.225,-0.25
  silkscreen extent -0.13,-0.13 2.37,1.38
"0805 COUPLER ANAREN" [mm] "Anaren 0805 Balun (BD1722J50100A00 etc)"
  rect 0.36x0.4 smd: 1(1.65,1.205) 2(1,1.205) 3(0.35,1.205) 4(0.35,0.045) 5(1,0.045) 6(1.65,0.045)
  silkscreen extent -0.13,-0.13 2.37,1.38
BDCN-7-25+ [mil] "Mini Circuits Coupler"
  rect 24x17.72 smd: 1(23.98,5.5) 2(62.98,5.5) 3(101.98,5.5) 4(101.98,57.5) 5(62.98,57.5) 6(23.98,57.5)
  silkscreen extent -10,-10 154,74
DL246-A [mm] "Kyocera DL-246 Grid Solder Mask"
  rect 0.4x0.4 smd paste+0.025 mask+0.025: 1(11.4,0.2) 2(11.4,11.4) 3(0.2,11.4) 4(0.2,0.2)
  L1 TOP region: 11.2,4.2 11.6,4.2 11.6,4.6 11.2,4.6
  L1 TOP region: 10.5,4.2 10.9,4.2 10.9,4.6 10.5,4.6
  L1 TOP region: 9.1,4.2 9.5,4.2 9.5,4.6 9.1,4.6
  L1 TOP region: 9.8,4.2 10.2,4.2 10.2,4.6 9.8,4.6
  L1 TOP region: 7.7,4.2 8.1,4.2 8.1,4.6 7.7,4.6
  L1 TOP region: 8.4,4.2 8.8,4.2 8.8,4.6 8.4,4.6
  L1 TOP region: 11.2,4.9 11.6,4.9 11.6,5.3 11.2,5.3
  L1 TOP region: 10.5,4.9 10.9,4.9 10.9,5.3 10.5,5.3
  L1 TOP region: 9.1,4.9 9.5,4.9 9.5,5.3 9.1,5.3
  L1 TOP region: 9.8,4.9 10.2,4.9 10.2,5.3 9.8,5.3
  L1 TOP region: 7.7,4.9 8.1,4.9 8.1,5.3 7.7,5.3
  L1 TOP region: 8.4,4.9 8.8,4.9 8.8,5.3 8.4,5.3
  L1 TOP region: 11.2,5.6 11.6,5.6 11.6,6 11.2,6
  L1 TOP region: 10.5,5.6 10.9,5.6 10.9,6 10.5,6
  L1 TOP region: 9.1,5.6 9.5,5.6 9.5,6 9.1,6
  L1 TOP region: 9.8,5.6 10.2,5.6 10.2,6 9.8,6
  L1 TOP region: 7.7,5.6 8.1,5.6 8.1,6 7.7,6
  L1 TOP region: 8.4,5.6 8.8,5.6 8.8,6 8.4,6
  L1 TOP region: 11.2,6.3 11.6,6.3 11.6,6.7 11.2,6.7
  L1 TOP region: 10.5,6.3 10.9,6.3 10.9,6.7 10.5,6.7
  L1 TOP region: 9.1,6.3 9.5,6.3 9.5,6.7 9.1,6.7
  L1 TOP region: 9.8,6.3 10.2,6.3 10.2,6.7 9.8,6.7
  L1 TOP region: 7.7,6.3 8.1,6.3 8.1,6.7 7.7,6.7
  L1 TOP region: 8.4,6.3 8.8,6.3 8.8,6.7 8.4,6.7
  L1 TOP region: 11.2,7 11.6,7 11.6,7.4 11.2,7.4
  L1 TOP region: 10.5,7 10.9,7 10.9,7.4 10.5,7.4
  L1 TOP region: 9.1,7 9.5,7 9.5,7.4 9.1,7.4
  L1 TOP region: 9.8,7 10.2,7 10.2,7.4 9.8,7.4
  L1 TOP region: 7.7,7 8.1,7 8.1,7.4 7.7,7.4
  L1 TOP region: 8.4,7 8.8,7 8.8,7.4 8.4,7.4
  L1 TOP region: 0.7,7 1.1,7 1.1,7.4 0.7,7.4
  L1 TOP region: 0,7 0.4,7 0.4,7.4 0,7.4
  L1 TOP region: 2.1,7 2.5,7 2.5,7.4 2.1,7.4
  L1 TOP region: 1.4,7 1.8,7 1.8,7.4 1.4,7.4
  L1 TOP region: 2.8,7 3.2,7 3.2,7.4 2.8,7.4
  L1 TOP region: 3.5,7 3.9,7 3.9,7.4 3.5,7.4
  L1 TOP region: 0.7,6.3 1.1,6.3 1.1,6.7 0.7,6.7
  L1 TOP region: 0,6.3 0.4,6.3 0.4,6.7 0,6.7
  L1 TOP region: 2.1,6.3 2.5,6.3 2.5,6.7 2.1,6.7
  L1 TOP region: 1.4,6.3 1.8,6.3 1.8,6.7 1.4,6.7
  L1 TOP region: 2.8,6.3 3.2,6.3 3.2,6.7 2.8,6.7
  L1 TOP region: 3.5,6.3 3.9,6.3 3.9,6.7 3.5,6.7
  L1 TOP region: 0.7,5.6 1.1,5.6 1.1,6 0.7,6
  L1 TOP region: 0,5.6 0.4,5.6 0.4,6 0,6
  L1 TOP region: 2.1,5.6 2.5,5.6 2.5,6 2.1,6
  L1 TOP region: 1.4,5.6 1.8,5.6 1.8,6 1.4,6
  L1 TOP region: 2.8,5.6 3.2,5.6 3.2,6 2.8,6
  L1 TOP region: 3.5,5.6 3.9,5.6 3.9,6 3.5,6
  L1 TOP region: 0.7,4.9 1.1,4.9 1.1,5.3 0.7,5.3
  L1 TOP region: 0,4.9 0.4,4.9 0.4,5.3 0,5.3
  L1 TOP region: 2.1,4.9 2.5,4.9 2.5,5.3 2.1,5.3
  L1 TOP region: 1.4,4.9 1.8,4.9 1.8,5.3 1.4,5.3
  L1 TOP region: 2.8,4.9 3.2,4.9 3.2,5.3 2.8,5.3
  L1 TOP region: 3.5,4.9 3.9,4.9 3.9,5.3 3.5,5.3
  L1 TOP region: 0.7,4.2 1.1,4.2 1.1,4.6 0.7,4.6
  L1 TOP region: 0,4.2 0.4,4.2 0.4,4.6 0,4.6
  L1 TOP region: 2.1,4.2 2.5,4.2 2.5,4.6 2.1,4.6
  L1 TOP region: 1.4,4.2 1.8,4.2 1.8,4.6 1.4,4.6
  L1 TOP region: 2.8,4.2 3.2,4.2 3.2,4.6 2.8,4.6
  L1 TOP region: 3.5,4.2 3.9,4.2 3.9,4.6 3.5,4.6
  L1 TOP region: 3.5,7.7 3.9,7.7 3.9,8.1 3.5,8.1
  L1 TOP region: 2.8,7.7 3.2,7.7 3.2,8.1 2.8,8.1
  L1 TOP region: 1.4,7.7 1.8,7.7 1.8,8.1 1.4,8.1
  L1 TOP region: 2.1,7.7 2.5,7.7 2.5,8.1 2.1,8.1
  L1 TOP region: 0,7.7 0.4,7.7 0.4,8.1 0,8.1
  L1 TOP region: 0.7,7.7 1.1,7.7 1.1,8.1 0.7,8.1
  L1 TOP region: 4.2,7.7 4.6,7.7 4.6,8.1 4.2,8.1
  L1 TOP region: 4.9,7.7 5.3,7.7 5.3,8.1 4.9,8.1
  L1 TOP region: 5.6,7.7 6,7.7 6,8.1 5.6,8.1
  L1 TOP region: 6.3,7.7 6.7,7.7 6.7,8.1 6.3,8.1
  L1 TOP region: 7,7.7 7.4,7.7 7.4,8.1 7,8.1
  L1 TOP region: 7.7,7.7 8.1,7.7 8.1,8.1 7.7,8.1
  L1 TOP region: 8.4,7.7 8.8,7.7 8.8,8.1 8.4,8.1
  L1 TOP region: 9.1,7.7 9.5,7.7 9.5,8.1 9.1,8.1
  L1 TOP region: 9.8,7.7 10.2,7.7 10.2,8.1 9.8,8.1
  L1 TOP region: 10.5,7.7 10.9,7.7 10.9,8.1 10.5,8.1
  L1 TOP region: 11.2,7.7 11.6,7.7 11.6,8.1 11.2,8.1
  L1 TOP region: 11.2,8.4 11.6,8.4 11.6,8.8 11.2,8.8
  L1 TOP region: 10.5,8.4 10.9,8.4 10.9,8.8 10.5,8.8
  L1 TOP region: 9.8,8.4 10.2,8.4 10.2,8.8 9.8,8.8
  L1 TOP region: 9.1,8.4 9.5,8.4 9.5,8.8 9.1,8.8
  L1 TOP region: 8.4,8.4 8.8,8.4 8.8,8.8 8.4,8.8
  L1 TOP region: 7.7,8.4 8.1,8.4 8.1,8.8 7.7,8.8
  L1 TOP region: 7,8.4 7.4,8.4 7.4,8.8 7,8.8
  L1 TOP region: 6.3,8.4 6.7,8.4 6.7,8.8 6.3,8.8
  L1 TOP region: 5.6,8.4 6,8.4 6,8.8 5.6,8.8
  L1 TOP region: 4.9,8.4 5.3,8.4 5.3,8.8 4.9,8.8
  L1 TOP region: 4.2,8.4 4.6,8.4 4.6,8.8 4.2,8.8
  L1 TOP region: 0.7,8.4 1.1,8.4 1.1,8.8 0.7,8.8
  L1 TOP region: 0,8.4 0.4,8.4 0.4,8.8 0,8.8
  L1 TOP region: 2.1,8.4 2.5,8.4 2.5,8.8 2.1,8.8
  L1 TOP region: 1.4,8.4 1.8,8.4 1.8,8.8 1.4,8.8
  L1 TOP region: 2.8,8.4 3.2,8.4 3.2,8.8 2.8,8.8
  L1 TOP region: 3.5,8.4 3.9,8.4 3.9,8.8 3.5,8.8
  L1 TOP region: 11.2,9.1 11.6,9.1 11.6,9.5 11.2,9.5
  L1 TOP region: 10.5,9.1 10.9,9.1 10.9,9.5 10.5,9.5
  L1 TOP region: 9.8,9.1 10.2,9.1 10.2,9.5 9.8,9.5
  L1 TOP region: 9.1,9.1 9.5,9.1 9.5,9.5 9.1,9.5
  L1 TOP region: 8.4,9.1 8.8,9.1 8.8,9.5 8.4,9.5
  L1 TOP region: 7.7,9.1 8.1,9.1 8.1,9.5 7.7,9.5
  L1 TOP region: 7,9.1 7.4,9.1 7.4,9.5 7,9.5
  L1 TOP region: 6.3,9.1 6.7,9.1 6.7,9.5 6.3,9.5
  L1 TOP region: 5.6,9.1 6,9.1 6,9.5 5.6,9.5
  L1 TOP region: 4.9,9.1 5.3,9.1 5.3,9.5 4.9,9.5
  L1 TOP region: 4.2,9.1 4.6,9.1 4.6,9.5 4.2,9.5
  L1 TOP region: 0.7,9.1 1.1,9.1 1.1,9.5 0.7,9.5
  L1 TOP region: 0,9.1 0.4,9.1 0.4,9.5 0,9.5
  L1 TOP region: 2.1,9.1 2.5,9.1 2.5,9.5 2.1,9.5
  L1 TOP region: 1.4,9.1 1.8,9.1 1.8,9.5 1.4,9.5
  L1 TOP region: 2.8,9.1 3.2,9.1 3.2,9.5 2.8,9.5
  L1 TOP region: 3.5,9.1 3.9,9.1 3.9,9.5 3.5,9.5
  L1 TOP region: 11.2,9.8 11.6,9.8 11.6,10.2 11.2,10.2
  L1 TOP region: 10.5,9.8 10.9,9.8 10.9,10.2 10.5,10.2
  L1 TOP region: 9.8,9.8 10.2,9.8 10.2,10.2 9.8,10.2
  L1 TOP region: 9.1,9.8 9.5,9.8 9.5,10.2 9.1,10.2
  L1 TOP region: 8.4,9.8 8.8,9.8 8.8,10.2 8.4,10.2
  L1 TOP region: 7.7,9.8 8.1,9.8 8.1,10.2 7.7,10.2
  L1 TOP region: 7,9.8 7.4,9.8 7.4,10.2 7,10.2
  L1 TOP region: 6.3,9.8 6.7,9.8 6.7,10.2 6.3,10.2
  L1 TOP region: 5.6,9.8 6,9.8 6,10.2 5.6,10.2
  L1 TOP region: 4.9,9.8 5.3,9.8 5.3,10.2 4.9,10.2
  L1 TOP region: 4.2,9.8 4.6,9.8 4.6,10.2 4.2,10.2
  L1 TOP region: 0.7,9.8 1.1,9.8 1.1,10.2 0.7,10.2
  L1 TOP region: 0,9.8 0.4,9.8 0.4,10.2 0,10.2
  L1 TOP region: 2.1,9.8 2.5,9.8 2.5,10.2 2.1,10.2
  L1 TOP region: 1.4,9.8 1.8,9.8 1.8,10.2 1.4,10.2
  L1 TOP region: 2.8,9.8 3.2,9.8 3.2,10.2 2.8,10.2
  L1 TOP region: 3.5,9.8 3.9,9.8 3.9,10.2 3.5,10.2
  L1 TOP region: 11.2,10.5 11.6,10.5 11.6,10.9 11.2,10.9
  L1 TOP region: 10.5,10.5 10.9,10.5 10.9,10.9 10.5,10.9
  L1 TOP region: 9.8,10.5 10.2,10.5 10.2,10.9 9.8,10.9
  L1 TOP region: 9.1,10.5 9.5,10.5 9.5,10.9 9.1,10.9
  L1 TOP region: 8.4,10.5 8.8,10.5 8.8,10.9 8.4,10.9
  L1 TOP region: 7.7,10.5 8.1,10.5 8.1,10.9 7.7,10.9
  L1 TOP region: 7,10.5 7.4,10.5 7.4,10.9 7,10.9
  L1 TOP region: 6.3,10.5 6.7,10.5 6.7,10.9 6.3,10.9
  L1 TOP region: 5.6,10.5 6,10.5 6,10.9 5.6,10.9
  L1 TOP region: 4.9,10.5 5.3,10.5 5.3,10.9 4.9,10.9
  L1 TOP region: 4.2,10.5 4.6,10.5 4.6,10.9 4.2,10.9
  L1 TOP region: 0.7,10.5 1.1,10.5 1.1,10.9 0.7,10.9
  L1 TOP region: 0,10.5 0.4,10.5 0.4,10.9 0,10.9
  L1 TOP region: 2.1,10.5 2.5,10.5 2.5,10.9 2.1,10.9
  L1 TOP region: 1.4,10.5 1.8,10.5 1.8,10.9 1.4,10.9
  L1 TOP region: 2.8,10.5 3.2,10.5 3.2,10.9 2.8,10.9
  L1 TOP region: 3.5,10.5 3.9,10.5 3.9,10.9 3.5,10.9
  L1 TOP region: 10.5,11.2 10.9,11.2 10.9,11.6 10.5,11.6
  L1 TOP region: 9.8,11.2 10.2,11.2 10.2,11.6 9.8,11.6
  L1 TOP region: 9.1,11.2 9.5,11.2 9.5,11.6 9.1,11.6
  L1 TOP region: 8.4,11.2 8.8,11.2 8.8,11.6 8.4,11.6
  L1 TOP region: 7.7,11.2 8.1,11.2 8.1,11.6 7.7,11.6
  L1 TOP region: 7,11.2 7.4,11.2 7.4,11.6 7,11.6
  L1 TOP region: 6.3,11.2 6.7,11.2 6.7,11.6 6.3,11.6
  L1 TOP region: 5.6,11.2 6,11.2 6,11.6 5.6,11.6
  L1 TOP region: 4.9,11.2 5.3,11.2 5.3,11.6 4.9,11.6
  L1 TOP region: 4.2,11.2 4.6,11.2 4.6,11.6 4.2,11.6
  L1 TOP region: 0.7,11.2 1.1,11.2 1.1,11.6 0.7,11.6
  L1 TOP region: 2.1,11.2 2.5,11.2 2.5,11.6 2.1,11.6
  L1 TOP region: 1.4,11.2 1.8,11.2 1.8,11.6 1.4,11.6
  L1 TOP region: 2.8,11.2 3.2,11.2 3.2,11.6 2.8,11.6
  L1 TOP region: 3.5,11.2 3.9,11.2 3.9,11.6 3.5,11.6
  L1 TOP region: 3.5,3.5 3.9,3.5 3.9,3.9 3.5,3.9
  L1 TOP region: 2.8,3.5 3.2,3.5 3.2,3.9 2.8,3.9
  L1 TOP region: 1.4,3.5 1.8,3.5 1.8,3.9 1.4,3.9
  L1 TOP region: 2.1,3.5 2.5,3.5 2.5,3.9 2.1,3.9
  L1 TOP region: 0,3.5 0.4,3.5 0.4,3.9 0,3.9
  L1 TOP region: 0.7,3.5 1.1,3.5 1.1,3.9 0.7,3.9
  L1 TOP region: 4.2,3.5 4.6,3.5 4.6,3.9 4.2,3.9
  L1 TOP region: 4.9,3.5 5.3,3.5 5.3,3.9 4.9,3.9
  L1 TOP region: 5.6,3.5 6,3.5 6,3.9 5.6,3.9
  L1 TOP region: 6.3,3.5 6.7,3.5 6.7,3.9 6.3,3.9
  L1 TOP region: 7,3.5 7.4,3.5 7.4,3.9 7,3.9
  L1 TOP region: 7.7,3.5 8.1,3.5 8.1,3.9 7.7,3.9
  L1 TOP region: 8.4,3.5 8.8,3.5 8.8,3.9 8.4,3.9
  L1 TOP region: 9.1,3.5 9.5,3.5 9.5,3.9 9.1,3.9
  L1 TOP region: 9.8,3.5 10.2,3.5 10.2,3.9 9.8,3.9
  L1 TOP region: 10.5,3.5 10.9,3.5 10.9,3.9 10.5,3.9
  L1 TOP region: 11.2,3.5 11.6,3.5 11.6,3.9 11.2,3.9
  L1 TOP region: 3.5,2.8 3.9,2.8 3.9,3.2 3.5,3.2
  L1 TOP region: 2.8,2.8 3.2,2.8 3.2,3.2 2.8,3.2
  L1 TOP region: 1.4,2.8 1.8,2.8 1.8,3.2 1.4,3.2
  L1 TOP region: 2.1,2.8 2.5,2.8 2.5,3.2 2.1,3.2
  L1 TOP region: 0,2.8 0.4,2.8 0.4,3.2 0,3.2
  L1 TOP region: 0.7,2.8 1.1,2.8 1.1,3.2 0.7,3.2
  L1 TOP region: 4.2,2.8 4.6,2.8 4.6,3.2 4.2,3.2
  L1 TOP region: 4.9,2.8 5.3,2.8 5.3,3.2 4.9,3.2
  L1 TOP region: 5.6,2.8 6,2.8 6,3.2 5.6,3.2
  L1 TOP region: 6.3,2.8 6.7,2.8 6.7,3.2 6.3,3.2
  L1 TOP region: 7,2.8 7.4,2.8 7.4,3.2 7,3.2
  L1 TOP region: 7.7,2.8 8.1,2.8 8.1,3.2 7.7,3.2
  L1 TOP region: 8.4,2.8 8.8,2.8 8.8,3.2 8.4,3.2
  L1 TOP region: 9.1,2.8 9.5,2.8 9.5,3.2 9.1,3.2
  L1 TOP region: 9.8,2.8 10.2,2.8 10.2,3.2 9.8,3.2
  L1 TOP region: 10.5,2.8 10.9,2.8 10.9,3.2 10.5,3.2
  L1 TOP region: 11.2,2.8 11.6,2.8 11.6,3.2 11.2,3.2
  L1 TOP region: 3.5,2.1 3.9,2.1 3.9,2.5 3.5,2.5
  L1 TOP region: 2.8,2.1 3.2,2.1 3.2,2.5 2.8,2.5
  L1 TOP region: 1.4,2.1 1.8,2.1 1.8,2.5 1.4,2.5
  L1 TOP region: 2.1,2.1 2.5,2.1 2.5,2.5 2.1,2.5
  L1 TOP region: 0,2.1 0.4,2.1 0.4,2.5 0,2.5
  L1 TOP region: 0.7,2.1 1.1,2.1 1.1,2.5 0.7,2.5
  L1 TOP region: 4.2,2.1 4.6,2.1 4.6,2.5 4.2,2.5
  L1 TOP region: 4.9,2.1 5.3,2.1 5.3,2.5 4.9,2.5
  L1 TOP region: 5.6,2.1 6,2.1 6,2.5 5.6,2.5
  L1 TOP region: 6.3,2.1 6.7,2.1 6.7,2.5 6.3,2.5
  L1 TOP region: 7,2.1 7.4,2.1 7.4,2.5 7,2.5
  L1 TOP region: 7.7,2.1 8.1,2.1 8.1,2.5 7.7,2.5
  L1 TOP region: 8.4,2.1 8.8,2.1 8.8,2.5 8.4,2.5
  L1 TOP region: 9.1,2.1 9.5,2.1 9.5,2.5 9.1,2.5
  L1 TOP region: 9.8,2.1 10.2,2.1 10.2,2.5 9.8,2.5
  L1 TOP region: 10.5,2.1 10.9,2.1 10.9,2.5 10.5,2.5
  L1 TOP region: 11.2,2.1 11.6,2.1 11.6,2.5 11.2,2.5
  L1 TOP region: 3.5,1.4 3.9,1.4 3.9,1.8 3.5,1.8
  L1 TOP region: 2.8,1.4 3.2,1.4 3.2,1.8 2.8,1.8
  L1 TOP region: 1.4,1.4 1.8,1.4 1.8,1.8 1.4,1.8
  L1 TOP region: 2.1,1.4 2.5,1.4 2.5,1.8 2.1,1.8
  L1 TOP region: 0,1.4 0.4,1.4 0.4,1.8 0,1.8
  L1 TOP region: 0.7,1.4 1.1,1.4 1.1,1.8 0.7,1.8
  L1 TOP region: 4.2,1.4 4.6,1.4 4.6,1.8 4.2,1.8
  L1 TOP region: 4.9,1.4 5.3,1.4 5.3,1.8 4.9,1.8
  L1 TOP region: 5.6,1.4 6,1.4 6,1.8 5.6,1.8
  L1 TOP region: 6.3,1.4 6.7,1.4 6.7,1.8 6.3,1.8
  L1 TOP region: 7,1.4 7.4,1.4 7.4,1.8 7,1.8
  L1 TOP region: 7.7,1.4 8.1,1.4 8.1,1.8 7.7,1.8
  L1 TOP region: 8.4,1.4 8.8,1.4 8.8,1.8 8.4,1.8
  L1 TOP region: 9.1,1.4 9.5,1.4 9.5,1.8 9.1,1.8
  L1 TOP region: 9.8,1.4 10.2,1.4 10.2,1.8 9.8,1.8
  L1 TOP region: 10.5,1.4 10.9,1.4 10.9,1.8 10.5,1.8
  L1 TOP region: 11.2,1.4 11.6,1.4 11.6,1.8 11.2,1.8
  L1 TOP region: 3.5,0.7 3.9,0.7 3.9,1.1 3.5,1.1
  L1 TOP region: 2.8,0.7 3.2,0.7 3.2,1.1 2.8,1.1
  L1 TOP region: 1.4,0.7 1.8,0.7 1.8,1.1 1.4,1.1
  L1 TOP region: 2.1,0.7 2.5,0.7 2.5,1.1 2.1,1.1
  L1 TOP region: 0,0.7 0.4,0.7 0.4,1.1 0,1.1
  L1 TOP region: 0.7,0.7 1.1,0.7 1.1,1.1 0.7,1.1
  L1 TOP region: 4.2,0.7 4.6,0.7 4.6,1.1 4.2,1.1
  L1 TOP region: 4.9,0.7 5.3,0.7 5.3,1.1 4.9,1.1
  L1 TOP region: 5.6,0.7 6,0.7 6,1.1 5.6,1.1
  L1 TOP region: 6.3,0.7 6.7,0.7 6.7,1.1 6.3,1.1
  L1 TOP region: 7,0.7 7.4,0.7 7.4,1.1 7,1.1
  L1 TOP region: 7.7,0.7 8.1,0.7 8.1,1.1 7.7,1.1
  L1 TOP region: 8.4,0.7 8.8,0.7 8.8,1.1 8.4,1.1
  L1 TOP region: 9.1,0.7 9.5,0.7 9.5,1.1 9.1,1.1
  L1 TOP region: 9.8,0.7 10.2,0.7 10.2,1.1 9.8,1.1
  L1 TOP region: 10.5,0.7 10.9,0.7 10.9,1.1 10.5,1.1
  L1 TOP region: 11.2,0.7 11.6,0.7 11.6,1.1 11.2,1.1
  L1 TOP region: 10.5,0 10.9,0 10.9,0.4 10.5,0.4
  L1 TOP region: 9.8,0 10.2,0 10.2,0.4 9.8,0.4
  L1 TOP region: 9.1,0 9.5,0 9.5,0.4 9.1,0.4
  L1 TOP region: 8.4,0 8.8,0 8.8,0.4 8.4,0.4
  L1 TOP region: 7.7,0 8.1,0 8.1,0.4 7.7,0.4
  L1 TOP region: 7,0 7.4,0 7.4,0.4 7,0.4
  L1 TOP region: 6.3,0 6.7,0 6.7,0.4 6.3,0.4
  L1 TOP region: 5.6,0 6,0 6,0.4 5.6,0.4
  L1 TOP region: 4.9,0 5.3,0 5.3,0.4 4.9,0.4
  L1 TOP region: 4.2,0 4.6,0 4.6,0.4 4.2,0.4
  L1 TOP region: 0.7,0 1.1,0 1.1,0.4 0.7,0.4
  L1 TOP region: 2.1,0 2.5,0 2.5,0.4 2.1,0.4
  L1 TOP region: 1.4,0 1.8,0 1.8,0.4 1.4,0.4
  L1 TOP region: 2.8,0 3.2,0 3.2,0.4 2.8,0.4
  L1 TOP region: 3.5,0 3.9,0 3.9,0.4 3.5,0.4
  silkscreen extent -0.2,-0.2 11.8,12.53
PORT-1_M [mil]
  rect 32x43 / inner round 32 / far side rect 32x43 hole 20: 1(0,0)
QFN50P-RFPAL-CHAR [mm]
  rect 1x0.28 smd: 1(4.5,-3.75) 2(4.5,-3.25) 3(4.5,-2.75) 4(4.5,-2.25) 5(4.5,-1.75) 6(4.5,-1.25) 7(4.5,-0.75) 8(4.5,-0.25) 9(4.5,0.25) 10(4.5,0.75) 11(4.5,1.25) 12(4.5,1.75) 13(4.5,2.25) 14(4.5,2.75) 15(4.5,3.25) 16(4.5,3.75) 33(-4.5,3.75) 34(-4.5,3.25) 35(-4.5,2.75) 36(-4.5,2.25) 37(-4.5,1.75) 38(-4.5,1.25) 39(-4.5,0.75) 40(-4.5,0.25) 41(-4.5,-0.25) 42(-4.5,-0.75) 43(-4.5,-1.25) 44(-4.5,-1.75) 45(-4.5,-2.25) 46(-4.5,-2.75) 47(-4.5,-3.25) 48(-4.5,-3.75)
  rect 0.28x1 smd: 17(3.75,4.5) 18(3.25,4.5) 19(2.75,4.5) 20(2.25,4.5) 21(1.75,4.5) 22(1.25,4.5) 23(0.75,4.5) 24(0.25,4.5) 25(-0.25,4.5) 26(-0.75,4.5) 27(-1.25,4.5) 28(-1.75,4.5) 29(-2.25,4.5) 30(-2.75,4.5) 31(-3.25,4.5) 32(-3.75,4.5) 49(-3.75,-4.5) 50(-3.25,-4.5) 51(-2.75,-4.5) 52(-2.25,-4.5) 53(-1.75,-4.5) 54(-1.25,-4.5) 55(-0.75,-4.5) 56(-0.25,-4.5) 57(0.25,-4.5) 58(0.75,-4.5) 59(1.25,-4.5) 60(1.75,-4.5) 61(2.25,-4.5) 62(2.75,-4.5) 63(3.25,-4.5) 64(3.75,-4.5)
  rect 7.58x7.58 smd: 65(0,0)
  silkscreen extent -5.1,-5.1 5.52,5.1

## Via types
v1: diameter 20, hole 10, L1 TOP to L4  BOT, tented both sides, 308 vias
v2: diameter 18/18/18/18 (per signal layer), hole 10, L1 TOP to L4  BOT, tented both sides, 175 vias
v3: diameter 18/18/18/18 (per signal layer), hole 10, L1 TOP to L4  BOT, 100 vias
v4: diameter 32/32/32/32 (per signal layer), hole 20, L1 TOP to L4  BOT, tented both sides, 3 vias
v5: diameter 18, hole 10, L1 TOP to L4  BOT, tented both sides, 3 vias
